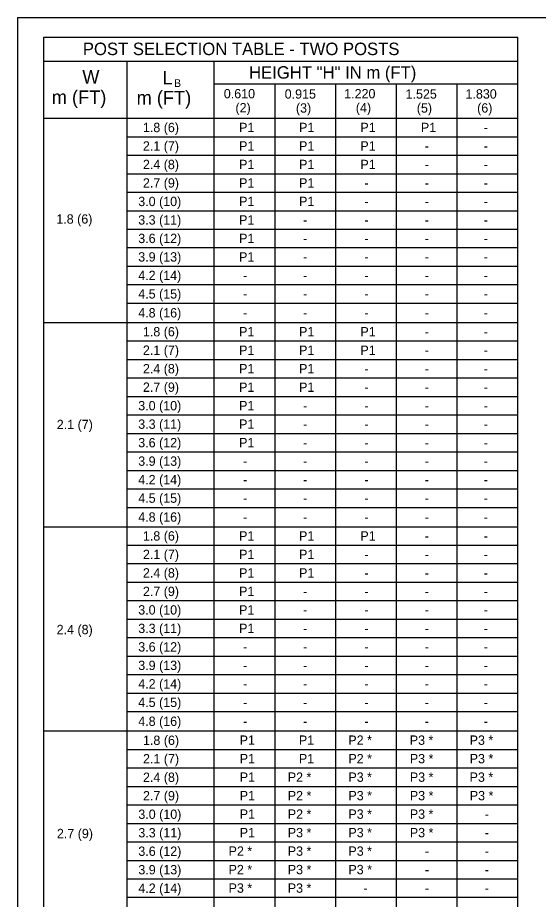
# Model space of a CAD drawing. Extents: x -1958 to 628, y -879 to 309.
# Drawn here: x -1077.4 to -910.1, y -582.8 to -299.6 of the extents above; entities that cross this region are included whole.
import ezdxf

# ---------------------------------------------------------------- set-up
doc = ezdxf.new("R2010")
doc.units = 0
for name, color, linetype in [('1', 7, 'Continuous'), ('2', 7, 'Continuous'), ('30', 7, 'Continuous')]:
    doc.layers.add(name, color=color, linetype=linetype)

msp = doc.modelspace()

# ---------------------------------------------------------------- linework, layer by layer
at = {"layer": '1'}
for p, q in [((-1077.39, -299.56), (-291.39, -299.56)), ((-1077.39, -299.56), (-1077.39, -863.56)), ((-1069, -331.88), (-1069, -305.86)), ((-1069, -305.86), (-916.65, -305.86)), ((-916.65, -331.88), (-916.65, -305.86)), ((-1069, -313.54), (-916.65, -313.54)), ((-1042.2, -331.88), (-1042.2, -313.54)), ((-1014.19, -331.88), (-1014.19, -313.54)), ((-994.68, -331.88), (-994.68, -320.88)), ((-975.17, -331.88), (-975.17, -320.88)), ((-955.67, -331.88), (-955.67, -320.88)), ((-936.16, -331.88), (-936.16, -320.88)), ((-1069, -856.76), (-1069, -331.88)), ((-1069, -331.88), (-916.65, -331.88)), ((-975.85, -331.88), (-940.21, -331.88)), ((-916.65, -856.76), (-916.65, -331.88)), ((-975.85, -528.71), (-940.21, -528.71)), ((-940.21, -528.71), (-916.65, -528.71))]:
    msp.add_line(p, q, dxfattribs=at)
at = {"layer": '2'}
for p, q in [((-1014.19, -320.88), (-916.65, -320.88)), ((-1042.2, -856.76), (-1042.2, -331.88)), ((-1014.19, -856.76), (-1014.19, -331.88)), ((-994.68, -856.76), (-994.68, -331.88)), ((-975.17, -856.76), (-975.17, -331.88)), ((-955.67, -856.76), (-955.67, -331.88)), ((-936.16, -856.76), (-936.16, -331.88)), ((-1042.2, -337.82), (-916.65, -337.82)), ((-975.85, -337.82), (-940.21, -337.82)), ((-940.21, -337.82), (-916.65, -337.82)), ((-1042.2, -343.76), (-916.65, -343.76)), ((-975.85, -343.76), (-940.21, -343.76)), ((-940.21, -343.76), (-916.65, -343.76)), ((-1042.2, -349.7), (-916.65, -349.7)), ((-975.85, -349.7), (-940.21, -349.7)), ((-940.21, -349.7), (-916.65, -349.7)), ((-1042.2, -355.64), (-916.65, -355.64)), ((-975.85, -355.64), (-940.21, -355.64)), ((-940.21, -355.64), (-916.65, -355.64)), ((-1042.2, -361.58), (-916.65, -361.58)), ((-975.85, -361.58), (-940.21, -361.58)), ((-940.21, -361.58), (-916.65, -361.58)), ((-1042.2, -367.52), (-916.65, -367.52)), ((-975.85, -367.52), (-940.21, -367.52)), ((-940.21, -367.52), (-916.65, -367.52)), ((-1042.2, -373.46), (-916.65, -373.46)), ((-975.85, -373.46), (-940.21, -373.46)), ((-940.21, -373.46), (-916.65, -373.46)), ((-1042.2, -379.4), (-916.65, -379.4)), ((-975.85, -379.4), (-940.21, -379.4)), ((-940.21, -379.4), (-916.65, -379.4)), ((-1042.2, -385.34), (-916.65, -385.34)), ((-975.85, -385.34), (-940.21, -385.34)), ((-940.21, -385.34), (-916.65, -385.34)), ((-1042.2, -391.28), (-916.65, -391.28)), ((-975.85, -391.28), (-940.21, -391.28)), ((-940.21, -391.28), (-916.65, -391.28)), ((-1069, -397.49), (-916.65, -397.49)), ((-975.85, -397.49), (-940.21, -397.49)), ((-940.21, -397.49), (-916.65, -397.49)), ((-1042.2, -403.43), (-916.65, -403.43)), ((-975.85, -403.43), (-940.21, -403.43)), ((-940.21, -403.43), (-916.65, -403.43)), ((-1042.2, -409.37), (-916.65, -409.37)), ((-975.85, -409.37), (-940.21, -409.37)), ((-940.21, -409.37), (-916.65, -409.37)), ((-1042.2, -415.31), (-916.65, -415.31)), ((-975.85, -415.31), (-940.21, -415.31)), ((-940.21, -415.31), (-916.65, -415.31)), ((-1042.2, -421.25), (-916.65, -421.25)), ((-975.85, -421.25), (-940.21, -421.25)), ((-940.21, -421.25), (-916.65, -421.25)), ((-1042.2, -427.19), (-916.65, -427.19)), ((-975.85, -427.19), (-940.21, -427.19)), ((-940.21, -427.19), (-916.65, -427.19)), ((-1042.2, -433.13), (-916.65, -433.13)), ((-975.85, -433.13), (-940.21, -433.13)), ((-940.21, -433.13), (-916.65, -433.13)), ((-1042.2, -439.07), (-916.65, -439.07)), ((-975.85, -439.07), (-940.21, -439.07)), ((-940.21, -439.07), (-916.65, -439.07)), ((-1042.2, -445.01), (-916.65, -445.01)), ((-975.85, -445.01), (-940.21, -445.01)), ((-940.21, -445.01), (-916.65, -445.01)), ((-1042.2, -450.95), (-916.65, -450.95)), ((-975.85, -450.95), (-940.21, -450.95)), ((-1042.2, -456.89), (-916.65, -456.89)), ((-975.85, -456.89), (-940.21, -456.89)), ((-1069, -463.1), (-916.65, -463.1)), ((-975.85, -463.1), (-940.21, -463.1)), ((-1042.2, -469.04), (-916.65, -469.04)), ((-975.85, -469.04), (-940.21, -469.04)), ((-1042.2, -474.98), (-916.65, -474.98)), ((-975.85, -474.98), (-940.21, -474.98)), ((-1042.2, -480.92), (-916.65, -480.92)), ((-975.85, -480.92), (-940.21, -480.92)), ((-1042.2, -486.86), (-916.65, -486.86)), ((-975.85, -486.86), (-940.21, -486.86)), ((-1042.2, -492.8), (-916.65, -492.8)), ((-975.85, -492.8), (-940.21, -492.8)), ((-1042.2, -498.74), (-916.65, -498.74)), ((-1042.2, -504.68), (-916.65, -504.68)), ((-1042.2, -510.62), (-916.65, -510.62)), ((-1042.2, -516.56), (-916.65, -516.56)), ((-1042.2, -522.5), (-916.65, -522.5)), ((-1069, -528.71), (-916.65, -528.71)), ((-1042.2, -534.65), (-916.65, -534.65)), ((-1042.2, -540.59), (-916.65, -540.59)), ((-1042.2, -546.53), (-916.65, -546.53)), ((-1042.2, -552.47), (-916.65, -552.47)), ((-1042.2, -558.41), (-916.65, -558.41)), ((-1042.2, -564.35), (-916.65, -564.35)), ((-1042.2, -570.29), (-916.65, -570.29)), ((-1042.2, -576.23), (-916.65, -576.23)), ((-1042.2, -582.17), (-916.65, -582.17))]:
    msp.add_line(p, q, dxfattribs=at)

# ---------------------------------------------------------------- texts
at = {"layer": '1'}
for s, height, p in [('POST SELECTION TABLE - TWO POSTS', 4.003, (-1056.42, -311.6)), ('W', 4.37, (-1056.6, -320.74)), ('L', 4.3, (-1030.81, -321.01)), ('HEIGHT "H" IN m (FT)', 4.003, (-1003.02, -319.17)), ('B', 2.5, (-1027.1, -321.84)), ('m (FT)', 4.375, (-1066.42, -327.3)), ('m (FT)', 4.375, (-1039.15, -327.47)), ('0.610', 3, (-1011.13, -325.49)), ('0.915', 3, (-991.57, -325.59)), ('1.220', 3, (-972.45, -325.49)), ('1.525', 3, (-952.73, -325.59)), ('1.830', 3, (-933.47, -325.57)), ('(2)', 3, (-1007.39, -329.99)), ('(3)', 3, (-987.96, -330.09)), ('(4)', 3, (-968.71, -329.99)), ('(5)', 3, (-949.12, -330.09)), ('(6)', 3, (-929.73, -330.07))]:
    msp.add_text(s, height=height, dxfattribs=at).set_placement(p)
at = {"layer": '2'}
for s, p in [('2.1 (7)', (-1037.13, -342.29)), ('P1', (-1006.23, -342.29)), ('P1', (-986.96, -342.29)), ('P1', (-967.25, -342.29)), ('-', (-946.52, -342.29)), ('-', (-927.58, -342.29)), ('2.4 (8)', (-1037.13, -348.23)), ('P1', (-1006.23, -348.23)), ('P1', (-986.96, -348.23)), ('P1', (-967.25, -348.23)), ('-', (-946.52, -348.23)), ('-', (-927.58, -348.23)), ('2.7 (9)', (-1037.13, -354.17)), ('P1', (-1006.23, -354.17)), ('P1', (-986.96, -354.17)), ('-', (-965.98, -354.17)), ('-', (-946.52, -354.17)), ('-', (-927.58, -354.17)), ('3.0 (10)', (-1038.63, -360.11)), ('P1', (-1006.23, -360.11)), ('P1', (-986.96, -360.11)), ('-', (-965.98, -360.11)), ('-', (-946.52, -360.11)), ('-', (-927.58, -360.11)), ('3.3 (11)', (-1038.63, -366.05)), ('P1', (-1006.23, -366.05)), ('-', (-985.69, -366.05)), ('-', (-965.98, -366.05)), ('-', (-946.52, -366.05)), ('-', (-927.58, -366.05)), ('3.6 (12)', (-1038.63, -371.99)), ('P1', (-1006.23, -371.99)), ('-', (-985.69, -371.99)), ('-', (-965.98, -371.99)), ('-', (-946.52, -371.99)), ('-', (-927.58, -371.99)), ('3.9 (13)', (-1038.63, -377.93)), ('P1', (-1006.23, -377.93)), ('-', (-985.69, -377.93)), ('-', (-965.98, -377.93)), ('-', (-946.52, -377.93)), ('-', (-927.58, -377.93)), ('4.2 (14)', (-1038.63, -383.87)), ('-', (-1004.95, -383.87)), ('-', (-985.69, -383.87)), ('-', (-965.98, -383.87)), ('-', (-946.52, -383.87)), ('-', (-927.58, -383.87)), ('4.5 (15)', (-1038.63, -389.81)), ('-', (-1004.95, -389.81)), ('-', (-985.69, -389.81)), ('-', (-965.98, -389.81)), ('-', (-946.52, -389.81)), ('-', (-927.58, -389.81)), ('4.8 (16)', (-1038.63, -395.89)), ('-', (-1004.95, -395.89)), ('-', (-985.69, -395.89)), ('-', (-965.98, -395.89)), ('-', (-946.52, -395.89)), ('-', (-927.58, -395.89)), ('1.8 (6)', (-1037.13, -401.96)), ('P1', (-1006.23, -401.96)), ('P1', (-986.96, -401.96)), ('P1', (-967.25, -401.96)), ('-', (-946.52, -401.96)), ('-', (-927.58, -401.96)), ('2.1 (7)', (-1037.13, -407.9)), ('P1', (-1006.23, -407.9)), ('P1', (-986.96, -407.9)), ('P1', (-967.25, -407.9)), ('-', (-946.52, -407.9)), ('-', (-927.58, -407.9)), ('2.4 (8)', (-1037.13, -413.84)), ('P1', (-1006.23, -413.84)), ('P1', (-986.96, -413.84)), ('-', (-965.98, -413.84)), ('-', (-946.52, -413.84)), ('-', (-927.58, -413.84)), ('2.7 (9)', (-1037.13, -419.78)), ('P1', (-1006.23, -419.78)), ('P1', (-986.96, -419.78)), ('-', (-965.98, -419.78)), ('-', (-946.52, -419.78)), ('-', (-927.58, -419.78)), ('3.0 (10)', (-1038.63, -425.72)), ('P1', (-1006.23, -425.72)), ('-', (-985.69, -425.72)), ('-', (-965.98, -425.72)), ('-', (-946.52, -425.72)), ('-', (-927.58, -425.72)), ('2.1 (7)', (-1064.81, -431.77)), ('3.3 (11)', (-1038.63, -431.66)), ('P1', (-1006.23, -431.66)), ('-', (-985.69, -431.66)), ('-', (-965.98, -431.66)), ('-', (-946.52, -431.66)), ('-', (-927.58, -431.66)), ('3.6 (12)', (-1038.63, -437.6)), ('P1', (-1006.23, -437.6)), ('-', (-985.69, -437.6)), ('-', (-965.98, -437.6)), ('-', (-946.52, -437.6)), ('-', (-927.58, -437.6)), ('3.9 (13)', (-1038.63, -443.54)), ('-', (-1004.95, -443.54)), ('-', (-985.69, -443.54)), ('-', (-965.98, -443.54)), ('-', (-946.52, -443.54)), ('-', (-927.58, -443.54)), ('4.2 (14)', (-1038.63, -449.48)), ('-', (-1004.95, -449.48)), ('-', (-985.69, -449.48)), ('-', (-965.98, -449.48)), ('-', (-946.52, -449.48)), ('-', (-927.58, -449.48)), ('4.5 (15)', (-1038.63, -455.42)), ('-', (-1004.95, -455.42)), ('-', (-985.69, -455.42)), ('-', (-965.98, -455.42)), ('-', (-946.52, -455.42)), ('-', (-927.58, -455.42)), ('4.8 (16)', (-1038.63, -461.5)), ('-', (-1004.95, -461.5)), ('-', (-985.69, -461.5)), ('-', (-965.98, -461.5)), ('-', (-946.52, -461.5)), ('-', (-927.58, -461.5)), ('1.8 (6)', (-1037.13, -467.57)), ('P1', (-1006.23, -467.57)), ('P1', (-986.96, -467.57)), ('P1', (-967.25, -467.57)), ('-', (-946.52, -467.57)), ('-', (-927.58, -467.57)), ('2.1 (7)', (-1037.13, -473.51)), ('P1', (-1006.23, -473.51)), ('P1', (-986.96, -473.51)), ('-', (-965.98, -473.51)), ('-', (-946.52, -473.51)), ('-', (-927.58, -473.51)), ('2.4 (8)', (-1037.13, -479.45)), ('P1', (-1006.23, -479.45)), ('P1', (-986.96, -479.45)), ('-', (-965.98, -479.45)), ('-', (-946.52, -479.45)), ('-', (-927.58, -479.45)), ('2.7 (9)', (-1037.13, -485.39)), ('P1', (-1006.23, -485.39)), ('-', (-985.69, -485.39)), ('-', (-965.98, -485.39)), ('-', (-946.52, -485.39)), ('-', (-927.58, -485.39)), ('3.0 (10)', (-1038.63, -491.33)), ('P1', (-1006.23, -491.33)), ('-', (-985.69, -491.33)), ('-', (-965.98, -491.33)), ('-', (-946.52, -491.33)), ('-', (-927.58, -491.33)), ('2.4 (8)', (-1064.85, -497.64)), ('3.3 (11)', (-1038.63, -497.27)), ('P1', (-1006.23, -497.27)), ('-', (-985.69, -497.27)), ('-', (-965.98, -497.27)), ('-', (-946.52, -497.27)), ('-', (-927.58, -497.27)), ('3.6 (12)', (-1038.63, -503.21)), ('-', (-1004.95, -503.21)), ('-', (-985.69, -503.21)), ('-', (-965.98, -503.21)), ('-', (-946.52, -503.21)), ('-', (-927.58, -503.21)), ('3.9 (13)', (-1038.63, -509.15)), ('-', (-1004.95, -509.15)), ('-', (-985.69, -509.15)), ('-', (-965.98, -509.15)), ('-', (-946.52, -509.15)), ('-', (-927.58, -509.15)), ('4.2 (14)', (-1038.63, -515.09)), ('-', (-1004.95, -515.09)), ('-', (-985.69, -515.09)), ('-', (-965.98, -515.09)), ('-', (-946.52, -515.09)), ('-', (-927.58, -515.09)), ('4.5 (15)', (-1038.63, -521.03)), ('-', (-1004.95, -521.03)), ('-', (-985.69, -521.03)), ('-', (-965.98, -521.03)), ('-', (-946.52, -521.03)), ('-', (-927.58, -521.03)), ('4.8 (16)', (-1038.63, -527.11)), ('-', (-1004.95, -527.11)), ('-', (-985.69, -527.11)), ('-', (-965.98, -527.11)), ('-', (-946.52, -527.11)), ('-', (-927.58, -527.11)), ('1.8 (6)', (-1037.1, -533.22)), ('P1', (-1006.04, -533.18)), ('P1', (-987.01, -533.18)), ('P2 *', (-971.12, -533.18)), ('P3 *', (-951.38, -533.18)), ('P3 *', (-932.13, -533.18)), ('2.1 (7)', (-1037.1, -539.16)), ('P1', (-1006.02, -539.12)), ('P1', (-987.01, -539.12)), ('P2 *', (-971.1, -539.12)), ('P3 *', (-951.36, -539.12)), ('P3 *', (-932.13, -539.12)), ('2.4 (8)', (-1037.1, -545.1)), ('P1', (-1006.02, -545.06)), ('P2 *', (-990.58, -545.06)), ('P3 *', (-971.1, -545.06)), ('P3 *', (-951.36, -545.06)), ('P3 *', (-932.15, -545.06)), ('2.7 (9)', (-1037.1, -551.04)), ('P1', (-1006.02, -551)), ('P2 *', (-990.58, -551)), ('P3 *', (-971.1, -551)), ('P3 *', (-951.36, -551)), ('P3 *', (-932.1, -551)), ('3.0 (10)', (-1038.6, -556.98)), ('P1', (-1006.02, -556.94)), ('P2 *', (-990.58, -556.94)), ('P3 *', (-971.1, -556.94)), ('P3 *', (-951.36, -556.94)), ('-', (-927.25, -556.94)), ('2.7 (9)', (-1064.77, -563.18)), ('3.3 (11)', (-1038.6, -562.92)), ('P1', (-1006.02, -562.88)), ('P3 *', (-990.58, -562.88)), ('P3 *', (-971.1, -562.88)), ('P3 *', (-951.36, -562.88)), ('-', (-927.25, -562.88)), ('3.6 (12)', (-1038.6, -568.86)), ('P2 *', (-1009.6, -568.82)), ('P3 *', (-990.58, -568.82)), ('P3 *', (-971.1, -568.82)), ('-', (-946.51, -568.82)), ('-', (-927.25, -568.82)), ('3.9 (13)', (-1038.6, -574.8)), ('P2 *', (-1009.6, -574.76)), ('P3 *', (-990.58, -574.76)), ('P3 *', (-971.1, -574.76)), ('-', (-946.51, -574.76)), ('-', (-927.25, -574.76)), ('4.2 (14)', (-1038.6, -580.74)), ('P3 *', (-1009.6, -580.7)), ('P3 *', (-990.58, -580.7)), ('-', (-966.25, -580.7)), ('-', (-946.51, -580.7)), ('-', (-927.25, -580.7))]:
    msp.add_text(s, height=3, dxfattribs=at).set_placement(p)
at = {"layer": '30'}
for s, p in [('1.8 (6)', (-1037.13, -336.35)), ('P1', (-1006.23, -336.35)), ('P1', (-986.96, -336.35)), ('P1', (-967.25, -336.35)), ('P1', (-947.8, -336.35)), ('-', (-927.58, -336.35)), ('1.8 (6)', (-1064.96, -365.75))]:
    msp.add_text(s, height=3, dxfattribs=at).set_placement(p)

doc.saveas('drawing.dxf')
